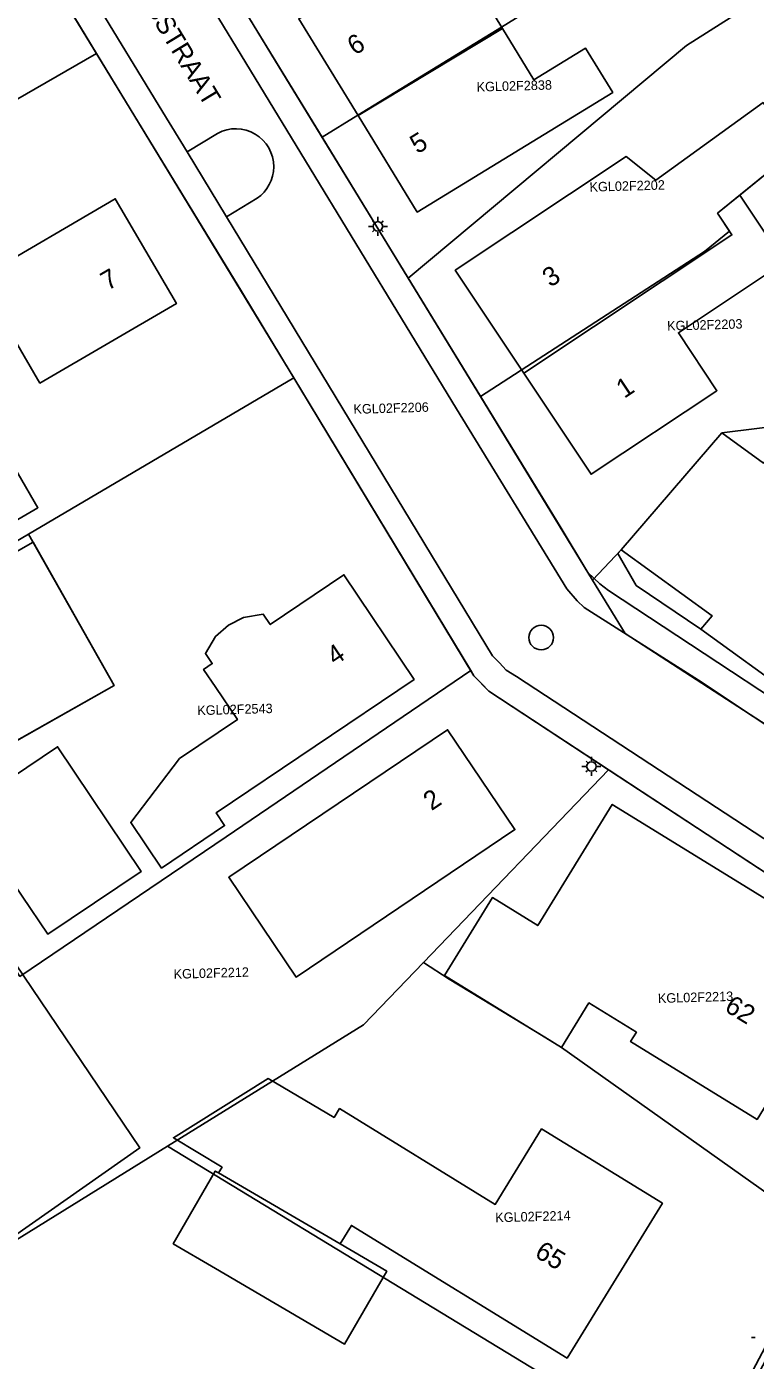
# Model space of a CAD drawing. Extents: x 124901 to 125496, y 515369 to 515789.
# Drawn here: x 125000.2 to 125038.7, y 515553.9 to 515624.4 of the extents above; entities that cross this region are included whole.
import ezdxf

# ---------------------------------------------------------------- set-up
doc = ezdxf.new("R2010")
doc.units = 0
for name, color, linetype in [('Gebouw', 7, 'Continuous'), ('Lichtmast', 7, 'Continuous'), ('Luifel', 7, 'Continuous'), ('Onbegroeid terrein', 7, 'Continuous'), ('Perceelnummers', 7, 'Continuous'), ('Perceelsgrenzen', 7, 'Continuous'), ('Putten', 7, 'Continuous'), ('Teksten', 7, 'Continuous'), ('Voetpad', 7, 'Continuous'), ('Wegen drempel verkeerseiland', 7, 'Continuous'), ('Wegen lokale weg', 7, 'Continuous')]:
    doc.layers.add(name, color=color, linetype=linetype)

msp = doc.modelspace()

# ---------------------------------------------------------------- linework, layer by layer
at = {"layer": 'Gebouw'}
for points in [[(125025.359, 515624.258), (125023.698, 515626.97), (125026.439, 515628.65), (125024.933, 515631.108), (125014.602, 515624.779), (125017.73, 515619.673)], [(125020.858, 515614.567), (125031.174, 515620.887), (125029.747, 515623.217), (125027.02, 515621.546), (125025.359, 515624.258), (125017.73, 515619.673)], [(125040.799, 515617.816), (125039.117, 515620.346), (125033.445, 515616.247), (125031.891, 515617.5), (125022.867, 515611.5), (125026.487, 515606.055), (125037.474, 515613.36), (125036.716, 515614.502), (125037.892, 515615.456)], [(124996.653, 515606.129), (124999.595, 515607.843), (125000.938, 515605.537), (125008.139, 515609.733), (125004.914, 515615.268), (124997.795, 515611.119), (124996.781, 515612.859), (124992.37, 515610.289), (124989.352, 515615.381), (124984.768, 515612.863), (124982.051, 515611.371), (124981.666, 515611.159), (124984.655, 515606.037), (124978.241, 515602.341), (124985.439, 515589.994), (125000.83, 515598.96)], [(125030.033, 515600.721), (125036.675, 515605.137), (125034.644, 515608.192), (125040.245, 515611.916), (125037.892, 515615.456), (125036.716, 515614.502), (125037.474, 515613.36), (125026.487, 515606.055)], [(125052.366, 515589.074), (125054.717, 515592.314), (125040.36, 515602.731), (125039.139, 515601.311), (125036.94, 515602.907), (125031.626, 515596.727), (125036.431, 515593.241), (125035.834, 515592.546), (125040.742, 515588.985), (125041.224, 515589.545), (125045.823, 515586.209), (125046.813, 515587.359), (125050.429, 515584.736), (125053.158, 515588.499)], [(124998.967, 515586.24), (125000, 515586.825), (125004.862, 515589.576), (125000.585, 515597.133), (124994.69, 515593.797)], [(125007.358, 515579.927), (125010.688, 515582.173), (125010.235, 515582.843), (125020.686, 515589.891), (125016.986, 515595.414), (125013.091, 515592.788), (125012.727, 515593.328), (125011.69, 515593.159), (125010.889, 515592.754), (125010.213, 515592.163), (125009.668, 515591.265), (125010.032, 515590.725), (125009.576, 515590.417), (125010.219, 515589.458), (125011.358, 515587.769), (125008.303, 515585.709), (125005.731, 515582.34)], [(125026.013, 515581.963), (125022.457, 515587.235), (125010.905, 515579.443), (125014.46, 515574.172)], [(124996.931, 515583.023), (125000, 515578.448), (125001.346, 515576.442), (125006.281, 515579.753), (125001.865, 515586.334)], [(125031.151, 515583.287), (125027.217, 515576.897), (125024.827, 515578.368), (125022.298, 515574.26), (125028.478, 515570.459), (125029.923, 515572.807), (125032.429, 515571.264), (125032.123, 515570.767), (125038.802, 515566.655), (125041.518, 515571.067), (125044.124, 515575.3), (125037.863, 515579.155)], [(124998.525, 515559.764), (125006.205, 515565.157), (124998.754, 515576.171), (124991.164, 515571.056), (124990.966, 515570.923), (124998.271, 515560.139)], [(125033.803, 515562.23), (125027.425, 515566.156), (125024.973, 515562.171), (125016.752, 515567.232), (125016.463, 515566.762), (125012.988, 515568.815), (125007.985, 515565.69), (125010.555, 515564.13), (125010.36, 515563.835), (125016.779, 515560.082), (125017.384, 515561.064), (125028.769, 515554.054)], [(125016.779, 515560.082), (125010.36, 515563.835), (125010.195, 515563.932), (125007.972, 515560.09), (125010.201, 515558.782), (125017.012, 515554.784), (125019.248, 515558.639)]]:
    msp.add_lwpolyline(points, close=True, dxfattribs=at)
at = {"layer": 'Lichtmast'}
for p, q in [((125018.481, 515613.814), (125018.281, 515613.813)), ((125018.569, 515614.025), (125018.499, 515614.096)), ((125018.781, 515614.113), (125018.781, 515614.313)), ((125018.993, 515614.025), (125019.064, 515614.097)), ((125019.081, 515613.813), (125019.281, 515613.813)), ((125018.569, 515613.601), (125018.497, 515613.53)), ((125018.781, 515613.513), (125018.781, 515613.313)), ((125018.993, 515613.601), (125019.063, 515613.53)), ((125029.838, 515585.509), (125029.768, 515585.58)), ((125030.05, 515585.597), (125030.05, 515585.797)), ((125030.262, 515585.509), (125030.333, 515585.581)), ((125029.75, 515585.298), (125029.55, 515585.297)), ((125029.838, 515585.085), (125029.766, 515585.014)), ((125030.05, 515584.997), (125030.05, 515584.797)), ((125030.262, 515585.085), (125030.332, 515585.014)), ((125030.35, 515585.297), (125030.55, 515585.297)), ((125038.698, 515555.149), (125038.498, 515555.148))]:
    msp.add_line(p, q, dxfattribs=at)
for centre in [(125018.781, 515613.813), (125030.05, 515585.297)]:
    msp.add_circle(centre, 0.25, dxfattribs=at)
at = {"layer": 'Luifel'}
msp.add_lwpolyline([(125031.626, 515596.727), (125031.453, 515596.532), (125032.414, 515594.855), (125035.834, 515592.546), (125036.431, 515593.241)], close=True, dxfattribs=at)
at = {"layer": 'Onbegroeid terrein'}
for points in [[(125002.396, 515640.583), (125013.566, 515622.216), (125028.402, 515597.96), (125029.863, 515595.54), (125030.494, 515594.946), (125030.959, 515594.579), (125045.442, 515585.041)], [(125035.4, 515546.426), (125041.156, 515557.703), (125041.651, 515558.673), (125043.145, 515562.119), (125043.544, 515563.105), (125043.748, 515563.61), (125045.321, 515567.498), (125045.546, 515568.055), (125046.874, 515572.577), (125047.038, 515574.017), (125046.969, 515574.62), (125038.47, 515580.19), (125024.631, 515589.269), (125024.258, 515589.652), (125023.849, 515590.085), (125011.59, 515610.348), (125000, 515629.377)], [(124997.795, 515611.119), (125004.914, 515615.268), (125008.139, 515609.733), (125000.938, 515605.537), (124999.595, 515607.843)], [(124996.653, 515606.129), (125000.83, 515598.96), (124985.439, 515589.994)]]:
    msp.add_lwpolyline(points, dxfattribs=at)
for points in [[(125031.174, 515620.887), (125020.858, 515614.567), (125017.73, 515619.673), (125014.602, 515624.779), (125024.933, 515631.108), (125026.439, 515628.65), (125023.698, 515626.97), (125025.359, 515624.258), (125027.02, 515621.546), (125029.747, 515623.217)], [(125036.675, 515605.137), (125030.033, 515600.721), (125026.487, 515606.055), (125022.867, 515611.5), (125031.891, 515617.5), (125033.445, 515616.247), (125039.117, 515620.346), (125040.799, 515617.816), (125037.892, 515615.456), (125040.245, 515611.916), (125034.644, 515608.192)], [(125054.717, 515592.314), (125052.366, 515589.074), (125053.158, 515588.499), (125050.429, 515584.736), (125046.813, 515587.359), (125045.823, 515586.209), (125041.224, 515589.545), (125040.742, 515588.985), (125035.834, 515592.546), (125036.431, 515593.241), (125031.626, 515596.727), (125036.94, 515602.907), (125039.139, 515601.311), (125040.36, 515602.731)], [(125000, 515586.825), (124998.967, 515586.24), (124994.69, 515593.797), (125000.585, 515597.133), (125004.862, 515589.576)], [(125010.688, 515582.173), (125007.358, 515579.927), (125005.731, 515582.34), (125008.303, 515585.709), (125011.358, 515587.769), (125010.219, 515589.458), (125009.576, 515590.417), (125010.032, 515590.725), (125009.668, 515591.265), (125010.213, 515592.163), (125010.889, 515592.754), (125011.69, 515593.159), (125012.727, 515593.328), (125013.091, 515592.788), (125016.986, 515595.414), (125020.686, 515589.891), (125010.235, 515582.843)], [(125022.457, 515587.235), (125026.013, 515581.963), (125014.46, 515574.172), (125010.905, 515579.443)], [(125000, 515578.448), (124996.931, 515583.023), (125001.865, 515586.334), (125006.281, 515579.753), (125001.346, 515576.442)], [(125027.217, 515576.897), (125031.151, 515583.287), (125037.863, 515579.155), (125044.124, 515575.3), (125041.518, 515571.067), (125038.802, 515566.655), (125032.123, 515570.767), (125032.429, 515571.264), (125029.923, 515572.807), (125028.478, 515570.459), (125022.298, 515574.26), (125024.827, 515578.368)], [(125006.205, 515565.157), (124998.525, 515559.764), (124998.271, 515560.139), (124990.966, 515570.923), (124991.164, 515571.056), (124998.754, 515576.171)], [(125027.425, 515566.156), (125033.803, 515562.23), (125028.769, 515554.054), (125017.384, 515561.064), (125016.779, 515560.082), (125019.248, 515558.639), (125017.012, 515554.784), (125010.201, 515558.782), (125007.972, 515560.09), (125010.195, 515563.932), (125010.36, 515563.835), (125010.555, 515564.13), (125007.985, 515565.69), (125012.988, 515568.815), (125016.463, 515566.762), (125016.752, 515567.232), (125024.973, 515562.171)]]:
    msp.add_lwpolyline(points, close=True, dxfattribs=at)
at = {"layer": 'Perceelsgrenzen'}
msp.add_lwpolyline([(124998.603, 515662.333), (125000.264, 515652.44), (125001.498, 515645.089), (125001.763, 515642.97), (125002.972, 515639.501), (125011.19, 515626.123), (125015.832, 515618.523), (125020.38, 515611.076), (125024.2, 515604.829), (125030.112, 515595.131), (125031.826, 515592.319), (125051.878, 515579.322), (125048.213, 515573.798), (125030.952, 515585.122), (125024.631, 515589.269), (125023.849, 515590.085), (125023.679, 515590.367), (125014.335, 515605.811), (125003.919, 515622.943), (124994.885, 515637.794)], dxfattribs=at)
for points in [[(125003.919, 515622.943), (124991.65, 515615.879), (124991.328, 515616.467), (124989.352, 515615.381), (124974.304, 515606.823), (124965.42, 515626.188), (124994.121, 515641.709), (124994.722, 515638.263), (124994.885, 515637.794)], [(125015.832, 515618.523), (125011.19, 515626.123), (125031.866, 515639.28), (125036.712, 515631.413), (125025.313, 515624.333), (125017.724, 515619.683)], [(125020.38, 515611.076), (125015.832, 515618.523), (125017.724, 515619.683), (125025.313, 515624.333), (125036.712, 515631.413), (125037.137, 515630.723), (125040.931, 515627.093), (125035.076, 515623.364)], [(125037.343, 515613.557), (125036.019, 515612.482), (125024.2, 515604.829), (125020.38, 515611.076), (125035.076, 515623.364), (125040.931, 515627.093), (125046.127, 515622.121), (125042.594, 515619.273), (125036.716, 515614.502)], [(125003.919, 515622.943), (125014.335, 515605.811), (125000.338, 515597.568), (124983.184, 515587.466), (124974.642, 515606.086), (124974.304, 515606.823), (124989.352, 515615.381), (124991.328, 515616.467), (124991.65, 515615.879)], [(125037.343, 515613.557), (125036.716, 515614.502), (125042.594, 515619.273), (125046.127, 515622.121), (125048.15, 515620.185), (125048.229, 515620.075), (125048.595, 515619.565), (125048.974, 515616.948), (125046.139, 515613.205), (125042.736, 515608.443), (125040.778, 515603.38), (125036.94, 515602.907), (125031.626, 515596.727), (125030.112, 515595.131), (125024.2, 515604.829), (125036.019, 515612.482)], [(125014.335, 515605.811), (125023.679, 515590.367), (125010.774, 515581.584), (124999.882, 515574.212), (124999.285, 515575.095), (124998.619, 515576.08), (124990.831, 515570.832), (124990.215, 515572.14), (124984.517, 515584.561), (124991.834, 515588.499), (124994.531, 515583.73), (125004.862, 515589.576), (125000.338, 515597.568)], [(125051.878, 515579.322), (125031.826, 515592.319), (125030.112, 515595.131), (125031.626, 515596.727), (125036.94, 515602.907), (125040.778, 515603.38), (125058.053, 515590.876)], [(124983.184, 515587.466), (125000.338, 515597.568), (125004.862, 515589.576), (124994.531, 515583.73), (124991.834, 515588.499), (124984.517, 515584.561)], [(125023.679, 515590.367), (125023.849, 515590.085), (125024.631, 515589.269), (125030.952, 515585.122), (125021.181, 515574.949), (125018.012, 515571.65), (125007.677, 515565.251), (124996.668, 515558.434), (124990.831, 515570.832), (124998.619, 515576.08), (124999.285, 515575.095), (124999.882, 515574.212), (125010.774, 515581.584)], [(125048.213, 515573.798), (125041.613, 515561.12), (125028.478, 515570.459), (125027.6, 515570.999), (125022.54, 515574.061), (125021.181, 515574.949), (125030.952, 515585.122)], [(125021.181, 515574.949), (125022.54, 515574.061), (125027.6, 515570.999), (125028.478, 515570.459), (125041.613, 515561.12), (125042.332, 515560.528), (125035.799, 515548.142), (125007.677, 515565.251), (125018.012, 515571.65)], [(124991.211, 515554.27), (124990.653, 515554.598), (124990.606, 515554.681), (124996.668, 515558.434), (125007.677, 515565.251), (125035.799, 515548.142), (125028.241, 515533.814), (125016.742, 515539.371), (125011.253, 515542.479), (125000.206, 515548.978)]]:
    msp.add_lwpolyline(points, close=True, dxfattribs=at)
at = {"layer": 'Putten'}
msp.add_circle((125027.4, 515592.1), 0.65, dxfattribs=at)
at = {"layer": 'Voetpad'}
for points in [[(125009.642, 515626.017), (125022.922, 515604.183), (125028.758, 515594.67), (125029.307, 515594.033), (125029.673, 515593.687), (125035.706, 515589.855), (125044.421, 515584.058), (125046.525, 515582.658), (125047.692, 515582.058), (125048.603, 515581.805), (125049.539, 515581.709), (125050.596, 515581.784), (125045.442, 515585.041), (125030.959, 515594.579), (125030.494, 515594.946), (125029.863, 515595.54), (125028.402, 515597.96), (125013.566, 515622.216), (125002.396, 515640.583)], [(125000, 515629.377), (125011.59, 515610.348), (125023.849, 515590.085), (125024.258, 515589.652), (125024.631, 515589.269), (125038.47, 515580.19), (125046.969, 515574.62), (125046.932, 515574.939), (125046.734, 515575.564), (125046.38, 515576.202), (125045.938, 515576.787), (125044.925, 515577.721), (125041.66, 515579.856), (125026.088, 515590.042), (125025.557, 515590.387), (125025.191, 515590.771), (125024.836, 515591.144), (125010.78, 515614.315), (125008.7, 515617.743), (125007.429, 515619.839), (125000, 515632.047)]]:
    msp.add_lwpolyline(points, dxfattribs=at)
at = {"layer": 'Wegen drempel verkeerseiland'}
msp.add_lwpolyline([(125010.315, 515618.724), (125008.7, 515617.743), (125010.78, 515614.315), (125012.396, 515615.297)], dxfattribs=at)
for centre, radius, start, end in [((125011.274, 515616.961), 2.007, 359.98656, 118.55866), ((125011.277, 515616.96), 2.004, 303.95155, 0.0358)]:
    msp.add_arc(centre, radius, start, end, dxfattribs=at)
at = {"layer": 'Wegen lokale weg'}
for points in [[(125005.883, 515628.428), (125007.557, 515629.444), (125000.96, 515640.29), (125000.81, 515640.547), (125000.755, 515640.807), (125000.684, 515641.291), (125000, 515645.34), (124996.221, 515667.71), (124993.89, 515681.429), (124988.898, 515680.647), (124992.261, 515660.592), (124995.968, 515638.742), (124996.093, 515638.472), (124996.31, 515638.11), (125000, 515632.047), (125007.429, 515619.839), (125008.7, 515617.743), (125010.315, 515618.724)], [(125029.307, 515594.033), (125028.758, 515594.67), (125022.922, 515604.183), (125009.642, 515626.017), (125007.965, 515624.999)], [(125012.396, 515615.297), (125010.78, 515614.315), (125024.836, 515591.144), (125025.191, 515590.771), (125025.557, 515590.387), (125026.088, 515590.042), (125041.66, 515579.856), (125044.421, 515584.058), (125035.706, 515589.855), (125029.673, 515593.687), (125029.307, 515594.033)]]:
    msp.add_lwpolyline(points, dxfattribs=at)
for centre, radius, start, end in [((125011.274, 515616.961), 2.007, 359.98656, 118.55866), ((125011.277, 515616.96), 2.004, 303.95155, 0.0358)]:
    msp.add_arc(centre, radius, start, end, dxfattribs=at)

# ---------------------------------------------------------------- texts
at = {"layer": 'Perceelnummers'}
for s, rotation, p in [('KGL02F2838', 1.63014, (125023.998, 515620.926)), ('KGL02F2202', 1.63021, (125029.959, 515615.642)), ('KGL02F2203', 1.63025, (125034.057, 515608.307)), ('KGL02F2206', 1.63006, (125017.495, 515603.913)), ('KGL02F2543', 1.62996, (125009.251, 515588.003)), ('KGL02F2212', 1.62995, (125007.999, 515574.082)), ('KGL02F2213', 1.63025, (125033.568, 515572.802)), ('KGL02F2214', 1.63015, (125024.983, 515561.227))]:
    msp.add_text(s, height=0.5, rotation=rotation, dxfattribs=at).set_placement(p)
at = {"layer": 'Teksten'}
for s, rotation, p in [('NICOLAAS KOPPESSTRAAT', 301.3, (125000.376, 515635.382)), ('6', 31.5, (125017.558, 515622.821)), ('5', 31.5, (125020.866, 515617.614)), ('7', 30.2, (125004.516, 515610.4)), ('3', 33.6, (125027.889, 515610.568)), ('1', 33.6, (125031.788, 515604.704)), ('4', 33.8, (125016.511, 515590.6)), ('2', 34, (125021.608, 515582.93)), ('62', 328.4, (125037.024, 515572.418)), ('65', 328.4, (125026.999, 515559.444))]:
    msp.add_text(s, height=1, rotation=rotation, dxfattribs=at).set_placement(p)

doc.saveas('drawing.dxf')
